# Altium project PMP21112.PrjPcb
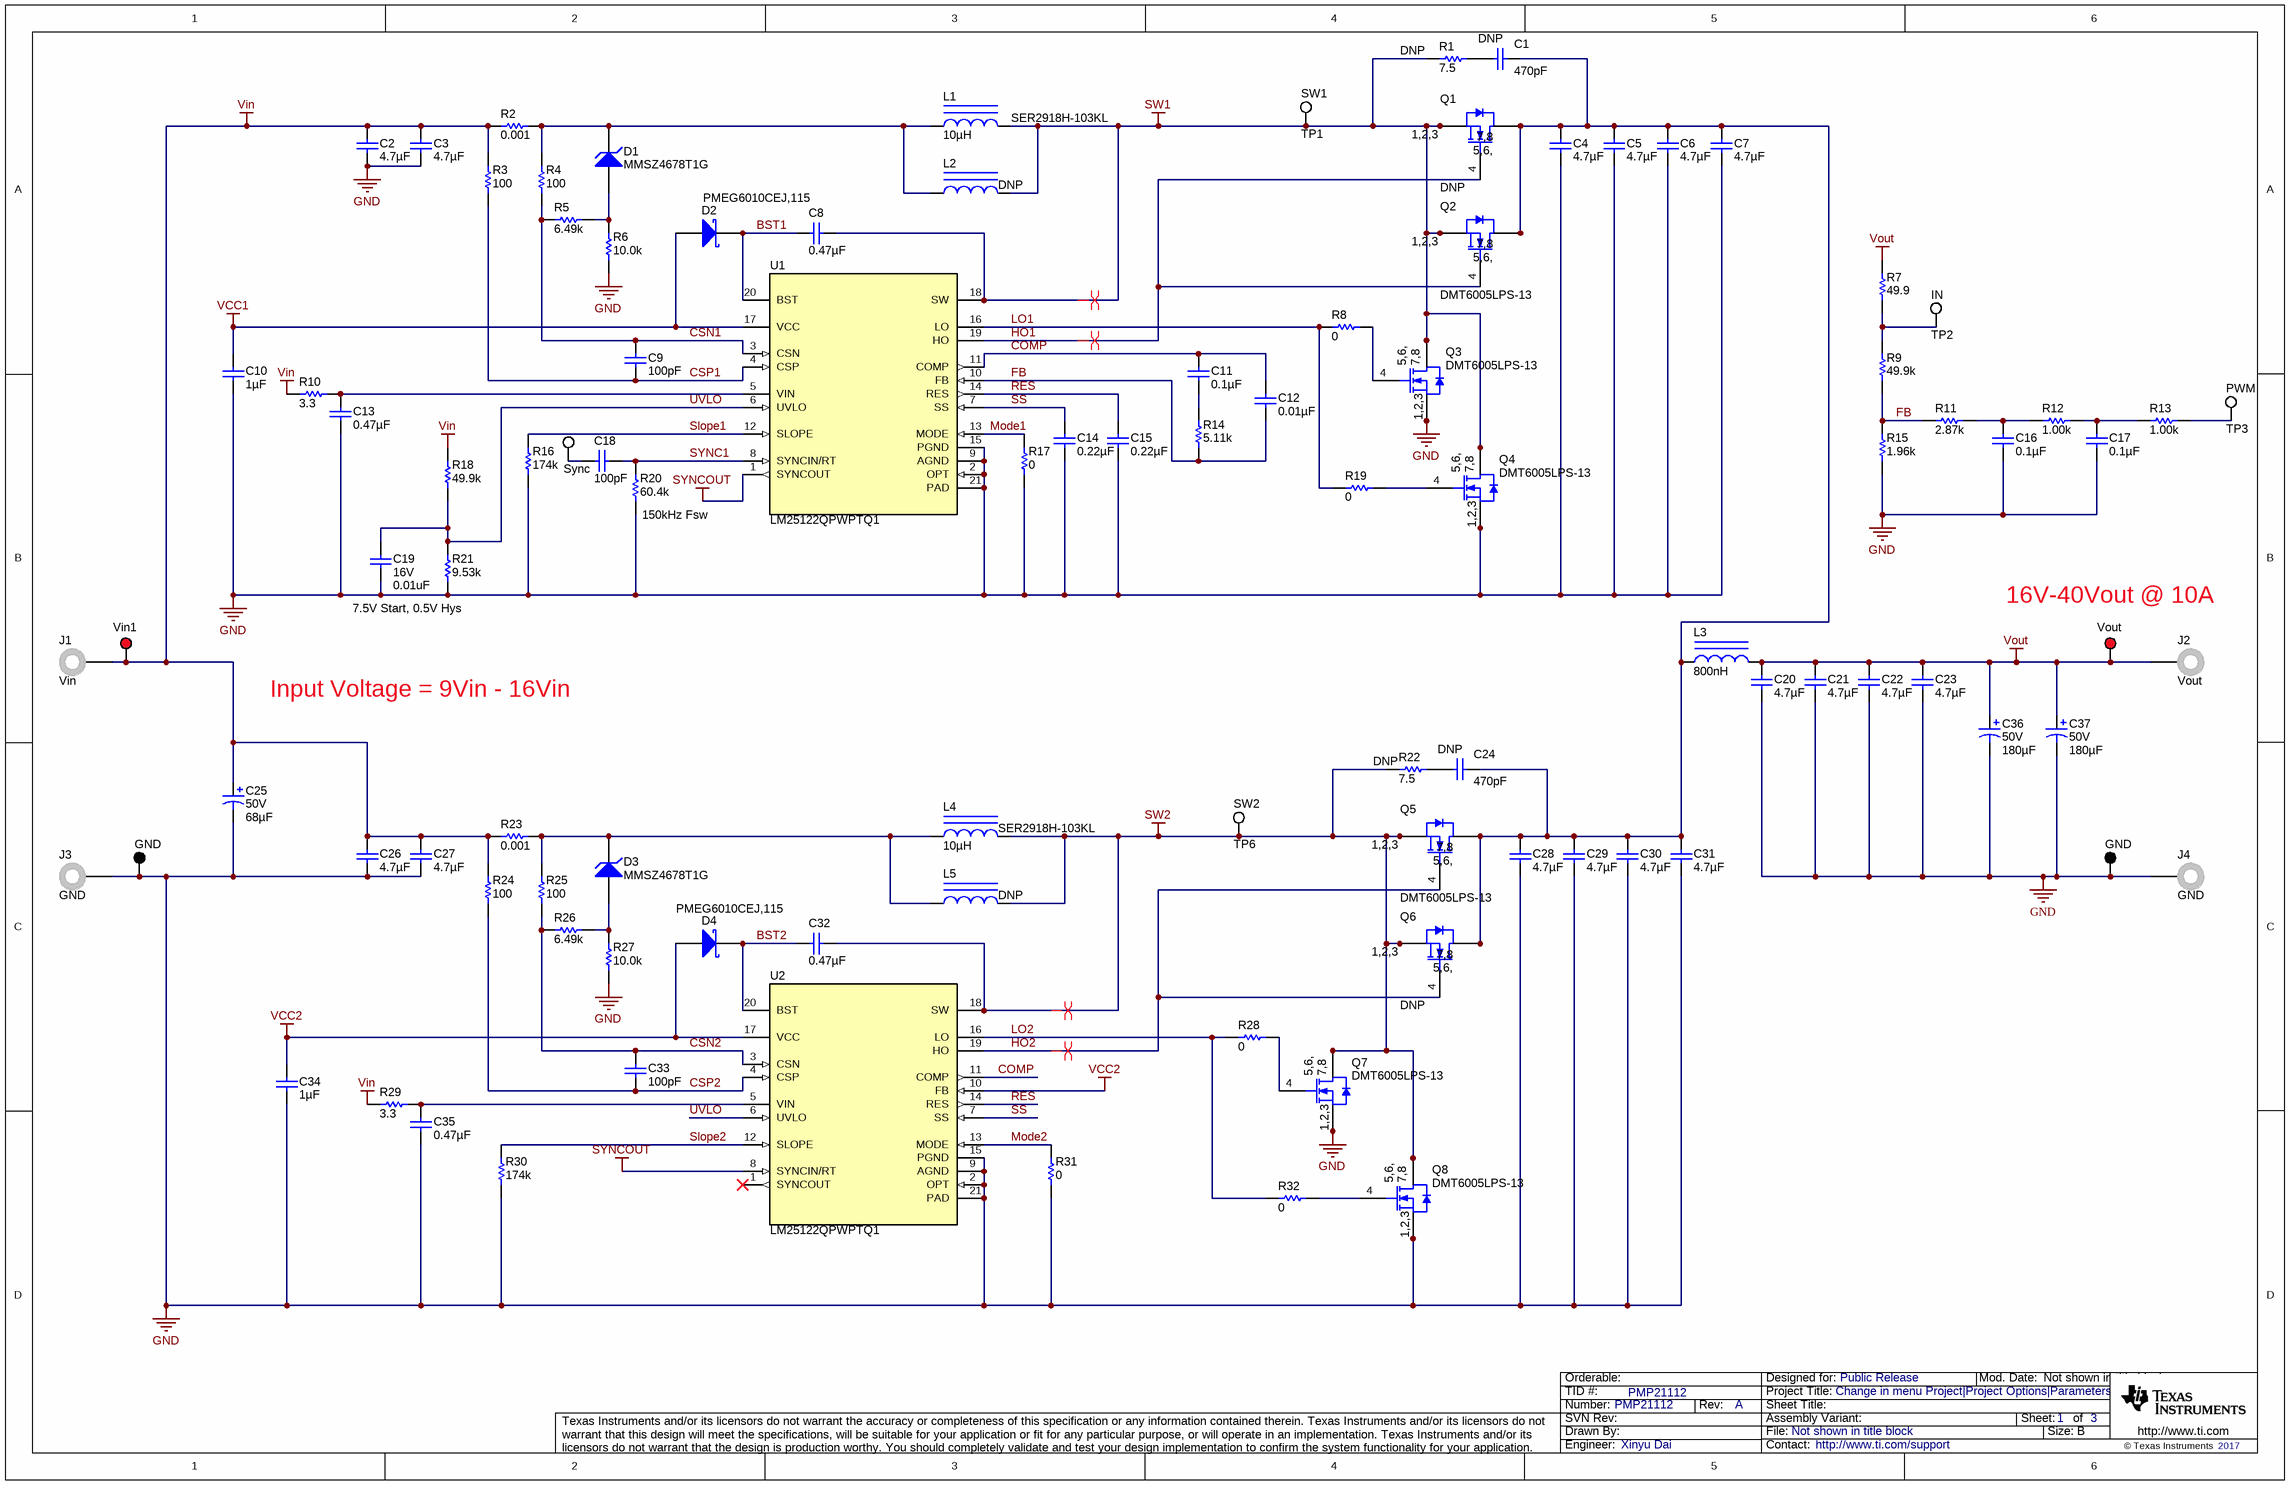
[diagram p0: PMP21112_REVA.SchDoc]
CopyrightYear: 2017; PCB_Layout: Xinyu; PCB_Rev: A; PRJ_Customer: Public Release; PRJ_Engineer: Xinyu Dai; PRJ_Number: PMP21112; PRJ_Title: Change in menu Project|Project Options|Parameters; SCH_Rev: A; TechSupport: http://www.ti.com/support; TID: PMP21112
2 sheets, 111 parts. Net scope: global (net labels, ports and power ports of the same name join across sheets).
Board file: PMP21112_REVA.PcbDoc
Sheets:
  PMP21112_REVA.SchDoc
  PMP21112_REVA_Hardware.SchDoc

## Sheet PMP21112_REVA.SchDoc
size 431 x 279 mm; Date: Not shown in title block; ApprovedBy: Not shown in title block; CheckedBy: Not shown in title block; Author: Not shown in title block; CompanyName: Not shown in title block; Engineer: Not shown in title block; Organization: Not shown in title block; Address1: Not shown in title block; Address2: Not shown in title block; Address3: Not shown in title block; Address4: Not shown in title block; DocumentNumber: 1; Revision: Use project parameter SCH_Rev; SheetNumber: 1; SheetTotal: 3; PageSetup: Record=PageOptions¦CenterHorizontal=True¦CenterVertical=True¦PrintScale=1.00¦XCorrection=1.00¦YCorrection=1.00¦PrintKind=0¦BorderSize=5000000¦LeftOffset=0¦BottomOffset=0¦Orientation=2¦PaperLength=1000¦PaperWidth=1000¦Scale=100¦PaperSource=15¦PrintQuality=600¦MediaType=1¦DitherType=10¦PaperKind=Letter¦PrintScaleMode=1

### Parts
C1  DNP  ValueDisplayed: 470pF  [0805L]
C2  ValueDisplayed: 4.7µF  [1210_270L]  (hidden comment: GRM32ER71K475KE14L)
C3  ValueDisplayed: 4.7µF  [1210_270L]  (hidden comment: GRM32ER71K475KE14L)
C4  ValueDisplayed: 4.7µF  [1210_270L]  (hidden comment: GRM32ER71K475KE14L)
C5  ValueDisplayed: 4.7µF  [1210_270L]  (hidden comment: GRM32ER71K475KE14L)
C6  ValueDisplayed: 4.7µF  [1210_270L]  (hidden comment: GRM32ER71K475KE14L)
C7  ValueDisplayed: 4.7µF  [1210_270L]  (hidden comment: GRM32ER71K475KE14L)
C8  ValueDisplayed: 0.47µF  [0603L]  (hidden comment: CGA3E3X7R1H474K080AE)
C9  ValueDisplayed: 100pF  [0402L]  (hidden comment: GRM1555C1H101JA01D)
C10  ValueDisplayed: 1µF  [0603L]  (hidden comment: GRM188R71E105KA12D)
C11  ValueDisplayed: 0.1µF  [0402L]  (hidden comment: GRM155R71H104ME14D)
C12  ValueDisplayed: 0.01µF  [0402L]  (hidden comment: GRM155R71H103KA88D)
C13  ValueDisplayed: 0.47µF  [0603L]  (hidden comment: CGA3E3X7R1H474K080AE)
C14  ValueDisplayed: 0.22µF  [0402]  (hidden comment: GRM155R71C224KA12D)
C15  ValueDisplayed: 0.22µF  [0402L]  (hidden comment: GRM155R71C224KA12D)
C16  ValueDisplayed: 0.1µF  [0402L]  (hidden comment: GRM155R71H104ME14D)
C17  ValueDisplayed: 0.1µF  [0402L]  (hidden comment: GRM155R71H104ME14D)
C18  ValueDisplayed: 100pF  [0402L]  (hidden comment: GRM1555C1H101JA01D)
C19  VDC_V: 16V  ValueDisplayed: 0.01uF  [0402L]  (hidden comment: GRM155R71C103KA01D)
C20  ValueDisplayed: 4.7µF  [1210_270L]  (hidden comment: GRM32ER71K475KE14L)
C21  ValueDisplayed: 4.7µF  [1210_270L]  (hidden comment: GRM32ER71K475KE14L)
C22  ValueDisplayed: 4.7µF  [1210_270L]  (hidden comment: GRM32ER71K475KE14L)
C23  ValueDisplayed: 4.7µF  [1210_270L]  (hidden comment: GRM32ER71K475KE14L)
C24  DNP  ValueDisplayed: 470pF  [0805L]
C25  VDC_V: 50V  ValueDisplayed: 68µF  [Panasonic_SMT_800x1020]  (hidden comment: EEH-ZA1H680V)
C26  ValueDisplayed: 4.7µF  [1210_270L]  (hidden comment: GRM32ER71K475KE14L)
C27  ValueDisplayed: 4.7µF  [1210_270L]  (hidden comment: GRM32ER71K475KE14L)
C28  ValueDisplayed: 4.7µF  [1210_270L]  (hidden comment: GRM32ER71K475KE14L)
C29  ValueDisplayed: 4.7µF  [1210_270L]  (hidden comment: GRM32ER71K475KE14L)
C30  ValueDisplayed: 4.7µF  [1210_270L]  (hidden comment: GRM32ER71K475KE14L)
C31  ValueDisplayed: 4.7µF  [1210_270L]  (hidden comment: GRM32ER71K475KE14L)
C32  ValueDisplayed: 0.47µF  [0603L]  (hidden comment: CGA3E3X7R1H474K080AE)
C33  ValueDisplayed: 100pF  [0402L]  (hidden comment: GRM1555C1H101JA01D)
C34  ValueDisplayed: 1µF  [0603L]  (hidden comment: GRM188R71E105KA12D)
C35  ValueDisplayed: 0.47µF  [0603L]  (hidden comment: CGA3E3X7R1H474K080AE)
C36  VDC_V: 50V  ValueDisplayed: 180µF  [SM_RADIAL_F]  (hidden comment: EEE-FK1H181SP)
C37  VDC_V: 50V  ValueDisplayed: 180µF  [SM_RADIAL_F]  (hidden comment: EEE-FK1H181SP)
D1  MMSZ4678T1G  [SOD-123]
D2  PMEG6010CEJ,115  [SOD-323F]
D3  MMSZ4678T1G  [SOD-123]
D4  PMEG6010CEJ,115  [SOD-323F]
J1  Vin  [Keystone_575-4]
J2  Vout  [Keystone_575-4]
J3  GND  [Keystone_575-4]
J4  GND  [Keystone_575-4]
L1  SER2918H-103KL  ValueDisplayed: 10µH  [SER2918H]
L2  DNP  [IHLP8787MZ]
L3  ValueDisplayed: 800nH  [XAL7070]  (hidden comment: XAL7070-801MEB)
L4  SER2918H-103KL  ValueDisplayed: 10µH  [SER2918H]
L5  DNP  [IHLP8787MZ]
Q1  DNP  [PowerDI5060-8]
Q2  DMT6005LPS-13  [PowerDI5060-8]
Q3  DMT6005LPS-13  [PowerDI5060-8]
Q4  DMT6005LPS-13  [PowerDI5060-8]
Q5  DMT6005LPS-13  [PowerDI5060-8]
Q6  DNP  [PowerDI5060-8]
Q7  DMT6005LPS-13  [PowerDI5060-8]
Q8  DMT6005LPS-13  [PowerDI5060-8]
R1  DNP  value 7.5  [2010L]
R2  ValueDisplayed: 0.001  [CRE2512-R1_R4]  (hidden comment: CRE2512-FZ-R001E-3)
R3  ValueDisplayed: 100  [0402L]  (hidden comment: CRCW0402100RFKED)
R4  ValueDisplayed: 100  [0402L]  (hidden comment: CRCW0402100RFKED)
R5  ValueDisplayed: 6.49k  [0402]  (hidden comment: CRCW04026K49FKED)
R6  ValueDisplayed: 10.0k  [0402L]  (hidden comment: CRCW040210K0FKED)
R7  ValueDisplayed: 49.9  [0402L]  (hidden comment: CRCW040249R9FKED)
R8  ValueDisplayed: 0  [0402L]  (hidden comment: CRCW04020000Z0ED)
R9  ValueDisplayed: 49.9k  [0402L]  (hidden comment: CRCW040249K9FKED)
R10  ValueDisplayed: 3.3  [0603L]  (hidden comment: CRCW06033R30JNEA)
R11  ValueDisplayed: 2.87k  [0402L]  (hidden comment: CRCW04022K87FKED)
R12  ValueDisplayed: 1.00k  [0402L]  (hidden comment: CRCW04021K00FKED)
R13  ValueDisplayed: 1.00k  [0402L]  (hidden comment: CRCW04021K00FKED)
R14  ValueDisplayed: 5.11k  [0402L]  (hidden comment: CRCW04025K11FKED)
R15  ValueDisplayed: 1.96k  [0402L]  (hidden comment: CRCW04021K96FKED)
R16  ValueDisplayed: 174k  [0402L]  (hidden comment: CRCW0402174KFKED)
R17  ValueDisplayed: 0  [0402L]  (hidden comment: CRCW04020000Z0ED)
R18  ValueDisplayed: 49.9k  [0402L]  (hidden comment: CRCW040249K9FKED)
R19  ValueDisplayed: 0  [0402L]  (hidden comment: CRCW04020000Z0ED)
R20  ValueDisplayed: 60.4k  [0402L]  (hidden comment: CRCW040260K4FKED)
R21  ValueDisplayed: 9.53k  [0402L]  (hidden comment: CRCW04029K53FKED)
R22  DNP  value 7.5  [2010L]
R23  ValueDisplayed: 0.001  [CRE2512-R1_R4]  (hidden comment: CRE2512-FZ-R001E-3)
R24  ValueDisplayed: 100  [0402L]  (hidden comment: CRCW0402100RFKED)
R25  ValueDisplayed: 100  [0402L]  (hidden comment: CRCW0402100RFKED)
R26  ValueDisplayed: 6.49k  [0402L]  (hidden comment: CRCW04026K49FKED)
R27  ValueDisplayed: 10.0k  [0402L]  (hidden comment: CRCW040210K0FKED)
R28  ValueDisplayed: 0  [0402L]  (hidden comment: CRCW04020000Z0ED)
R29  ValueDisplayed: 3.3  [0603L]  (hidden comment: CRCW06033R30JNEA)
R30  ValueDisplayed: 174k  [0402L]  (hidden comment: CRCW0402174KFKED)
R31  ValueDisplayed: 0  [0402L]  (hidden comment: CRCW04020000Z0ED)
R32  ValueDisplayed: 0  [0402L]  (hidden comment: CRCW04020000Z0ED)
Sync  5002  [Keystone5002]  (value not drawn)
TP1  SW1  [Keystone5002]
TP2  IN  [Keystone5002]
TP3  PWM  [Keystone5002]
TP4  GND  [Keystone5001]
TP5  GND  [Keystone5001]
TP6  SW2  [Keystone5002]
U1  LM25122QPWPTQ1  [PWP0020A_N]
U2  LM25122QPWPTQ1  [PWP0020A_N]
Vin1  5000  [Keystone5000]  (value not drawn)
Vout  5000  [Keystone5000]  (value not drawn)

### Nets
GND: C2.2 C3.2 C4.2 C5.2 C6.2 C7.2 C10.2 C13.2 C14.2 C15.2 C16.2 C17.2 C19.2 C20.2 C21.2 C22.2 C23.2 C25.2(-) C26.2 C27.2 C28.2 C29.2 C30.2 C31.2 C34.2 C35.2 C36.2(-) C37.2(-) J3.1 J4.1 Q3.1(S) Q3.2(S) Q3.3(S) Q4.1(S) Q4.2(S) Q4.3(S) Q7.1(S) Q7.2(S) Q7.3(S) Q8.1(S) Q8.2(S) Q8.3(S) R6.1 R15.1 R16.1 R17.1 R20.1 R21.1 R27.1 R30.1 R31.1 TP4.1 TP5.1 U1.2(OPT) U1.9(AGND) U1.15(PGND) U1.21(PAD) U2.2(OPT) U2.9(AGND) U2.15(PGND) U2.21(PAD)
SW1: C8.2 L1.1 L2.1 Q1.1(S) Q1.2(S) Q1.3(S) Q2.1(S) Q2.2(S) Q2.3(S) Q3.5(D) Q3.6(D) Q3.7(D) Q3.8(D) Q3.9(D) Q4.5(D) Q4.6(D) Q4.7(D) Q4.8(D) Q4.9(D) R1.2 TP1.1 U1.18(SW)
SW2: C32.2 L4.2 L5.1 Q5.1(S) Q5.2(S) Q5.3(S) Q6.1(S) Q6.2(S) Q6.3(S) Q7.5(D) Q7.6(D) Q7.7(D) Q7.8(D) Q7.9(D) Q8.5(D) Q8.6(D) Q8.7(D) Q8.8(D) Q8.9(D) R22.2 TP6.1 U2.18(SW)
SYNCOUT: U1.1(SYNCOUT) U2.8(SYNCIN/RT)
VCC1: C10.1 D2.2(A) U1.17(VCC)
VCC2: C34.1 D4.2(A) U2.10(FB) U2.17(VCC)
Vin: C2.1 C3.1 C25.1(+) C26.1 C27.1 J1.1 R2.1 R3.2 R10.1 R18.2 R23.1 R24.2 R29.1 Vin1.1
Vout: C20.1 C21.1 C22.1 C23.1 C36.1(+) C37.1(+) J2.1 L3.2 R7.1 Vout.1
BST1: C8.1 D2.1(K) U1.20(BST)
BST2: C32.1 D4.1(K) U2.20(BST)
COMP: C11.1 C12.1 U1.11(COMP) U2.11(COMP)
CSN1: C9.1 R4.1 R5.1 U1.3(CSN)
CSN2: C33.1 R25.1 R26.1 U2.3(CSN)
CSP1: C9.2 R3.1 U1.4(CSP)
CSP2: C33.2 R24.1 U2.4(CSP)
FB: C12.2 R9.2 R11.1 R14.1 R15.2 U1.10(FB)
HO1: Q1.4(G) Q2.4(G) U1.19(HO)
HO2: Q5.4(G) Q6.4(G) U2.19(HO)
LO1: R8.2 R19.2 U1.16(LO)
LO2: R28.2 R32.2 U2.16(LO)
Mode1: R17.2 U1.13(MODE)
Mode2: R31.2 U2.13(MODE)
RES: C15.1 U1.14(RES) U2.14(RES)
Slope1: R16.2 U1.12(SLOPE)
Slope2: R30.2 U2.12(SLOPE)
SS: C14.1 U1.7(SS) U2.7(SS)
SYNC1: C18.1 R20.2 U1.8(SYNCIN/RT)
UVLO: C19.1 R18.1 R21.2 U1.6(UVLO) U2.6(UVLO)
NetC1_1: C1.1 C4.1 C5.1 C6.1 C7.1 C24.1 C28.1 C29.1 C30.1 C31.1 L3.1 Q1.5(D) Q1.6(D) Q1.7(D) Q1.8(D) Q1.9(D) Q2.5(D) Q2.6(D) Q2.7(D) Q2.8(D) Q2.9(D) Q5.5(D) Q5.6(D) Q5.7(D) Q5.8(D) Q5.9(D) Q6.5(D) Q6.6(D) Q6.7(D) Q6.8(D) Q6.9(D)
NetC1_2: C1.2 R1.1
NetC11_2: C11.2 R14.2
NetC13_1: C13.1 R10.2 U1.5(VIN)
NetC16_1: C16.1 R11.2 R12.1
NetC17_1: C17.1 R12.2 R13.1
NetC18_2: C18.2 Sync.1
NetC24_2: C24.2 R22.1
NetC35_1: C35.1 R29.2 U2.5(VIN)
NetD1_1: D1.1(K) L1.2 L2.2 R2.2 R4.2
NetD1_2: D1.2(A) R5.2 R6.2
NetD3_1: D3.1(K) L4.1 L5.2 R23.2 R25.2
NetD3_2: D3.2(A) R26.2 R27.2
NetQ3_4: Q3.4(G) R8.1
NetQ4_4: Q4.4(G) R19.1
NetQ7_4: Q7.4(G) R28.1
NetQ8_4: Q8.4(G) R32.1
NetR7_2: R7.2 R9.1 TP2.1
NetR13_2: R13.2 TP3.1

Not connected (* = marked no-connect by the designer): U2 1(SYNCOUT)*

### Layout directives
differential pair: HO1, HO2, SW1, SW2

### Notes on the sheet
- (near R20) 150kHz Fsw
- 7.5V Start, 0.5V Hys
- 16V-40Vout @ 10A
- Input Voltage = 9Vin - 16Vin

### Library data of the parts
C1 C24 = GRM2165C2A471JA01D: CAP, CERM, 470pF, 100V, +/-5%, C0G/NP0, 0805; Manufacturer: MuRata; Polarized: N; CompType: Capacitor; U/M: EA; Cap_F: 0.00000000047; Tolerance_%: 5; VDC_V: 100; TaMin_C: -55; TaMax_C: 125; Cap_Case: 0805
C2-C7 C20-C23 C26-C31 = GRM32ER71K475KE14L: CAP, CERM, 4.7 µF, 80 V, +/- 10%, X7R, 1210; Manufacturer: MuRata; Polarized: N; CompType: Capacitor; Value: 4.7uF; U/M: EA; Cap_F: 0.0000047; Tolerance_%: 10; Value1: Unknown; VDC_V: 80; Value2: 80V; TaMin_C: -55; TaMax_C: 125; Cap_Case: 1210; SizeArea_mm2: 8; SizeAreaWB_mm2: 14.7; SizeX_mm: 3.2; SizeY_mm: 2.5; SizeZ_mm: 2.7; AEC Category: Q200
C8 C13 C32 C35 = CGA3E3X7R1H474K080AE: CAP, CERM, 0.47 µF, 50 V,+/- 10%, X7R, AEC-Q200 Grade 1, 0603; Manufacturer: TDK; Polarized: N; CompType: Capacitor; Value: 0.47uF; U/M: EA; Cap_F: 0.00000047; Tolerance_%: 10; VDC_V: 50; Value2: 50V; TaMin_C: -55; TaMax_C: 125; Cap_Case: 0603; SizeArea_mm2: 1.28; SizeAreaWB_mm2: 4.68; SizeX_mm: 1.6; SizeY_mm: 0.8; SizeZ_mm: 1; AEC Category: Q200; AEC Qualified: Y
C9 C18 C33 = GRM1555C1H101JA01D: CAP, CERM, 100 pF, 50 V,+/- 5%, C0G/NP0, 0402; Manufacturer: MuRata; Polarized: N; CompType: Capacitor; Value: 100pF; U/M: EA; Cap_F: 0.0000000001; Tolerance_%: 5; VDC_V: 50; Value2: 50V; TaMin_C: -55; TaMax_C: 125; Cap_Case: 0402; SizeArea_mm2: 0.5; SizeAreaWB_mm2: 3; SizeX_mm: 1; SizeZ_mm: 0.6; AEC Category: Q200; Green_Lifecycle: Active; Green_REACh: Passed
C10 C34 = GRM188R71E105KA12D: CAP, CERM, 1uF, 25V, +/-10%, X7R, 0603; Manufacturer: MuRata; Polarized: N; CompType: Capacitor; U/M: EA; Cap_F: 0.000001; Tolerance_%: 10; VDC_V: 25; TaMin_C: -55; TaMax_C: 125; Cap_Case: 0603
C11 C16 C17 = GRM155R71H104ME14D: CAP, CERM, 0.1 µF, 50 V,+/- 20%, X7R, 0402; Manufacturer: MuRata; Polarized: N; CompType: Capacitor; Value: 0.1uF; U/M: EA; Cap_F: 0.0000001; Tolerance_%: 20; VDC_V: 50; Value2: 50V; TaMin_C: -55; TaMax_C: 125; Cap_Case: 0402; SizeArea_mm2: 0.5; SizeAreaWB_mm2: 3; SizeX_mm: 1; SizeZ_mm: 0.6; AEC Category: Q200
C12 = GRM155R71H103KA88D: CAP, CERM, 0.01 µF, 50 V,+/- 10%, X7R, 0402; Manufacturer: MuRata; Polarized: N; CompType: Capacitor; Value: 0.01uF; U/M: EA; Cap_F: 0.00000001; Tolerance_%: 10; VDC_V: 50; Value2: 50V; TaMin_C: -55; TaMax_C: 125; Cap_Case: 0402; SizeArea_mm2: 0.5; SizeAreaWB_mm2: 3; SizeX_mm: 1; SizeZ_mm: 0.6; AEC Category: Q200; Green_Lifecycle: Active; Green_REACh: Passed
C14 = GRM155R71C224KA12D: CAP, CERM, 0.22 µF, 16 V,+/- 10%, X7R, 0402; Manufacturer: MuRata; Polarized: N; CompType: Capacitor; Value: 0.22uF; U/M: EA; Cap_F: 0.00000022; Tolerance_%: 10; VDC_V: 16; Value2: 16V; TaMin_C: -55; TaMax_C: 125; SizeArea_mm2: 0.5; SizeAreaWB_mm2: 3; SizeX_mm: 1; SizeZ_mm: 0.6; AEC Category: Q200; Green_Lifecycle: Active; Green_REACh: Passed
C15 = GRM155R71C224KA12D: CAP, CERM, 0.22 µF, 16 V,+/- 10%, X7R, 0402; Manufacturer: MuRata; Polarized: N; CompType: Capacitor; Value: 0.22uF; U/M: EA; Cap_F: 0.00000022; Tolerance_%: 10; VDC_V: 16; Value2: 16V; TaMin_C: -55; TaMax_C: 125; Cap_Case: 0402; SizeArea_mm2: 0.5; SizeAreaWB_mm2: 3; SizeX_mm: 1; SizeZ_mm: 0.6; AEC Category: Q200; Green_Lifecycle: Active; Green_REACh: Passed
C19 = CMP-0006639-2: CAP, CERM, 0.01 uF, 16 V, +/- 10%, X7R, 0402; Manufacturer: MuRata; TaMin_C: -55°C; Polarized: N; SizeAreaWB_mm2: 3; Value1: Unknown; U/M: EA; Value: 0.01uF; TaMax_C: 125°C; SizeZ_mm: 0.6; SizeX_mm: 1; SizeY_mm: 0.5; Cap_Case: 0402; Cap_F: 10nF; AEC Category: Q200
C25 = CMP-0077288-1: CAP, Aluminum Polymer, 68 µF, 50 V,+/- 20%, 0.03 ohm, AEC-Q200 Grade 2, D8xL10.2mm SMD; Manufacturer: Panasonic; IRMS_A: 1.8A; SizeAreaWB_mm2: 106.09; SizeArea_mm2: 68.89; AEC Qualified: Y; AEC Category: Q200; Value: 68uF; TaMax_C: 105°C; SizeZ_mm: 10.5; AEC Grade: 2; TaMin_C: -55°C; SizeY_mm: 8.3; U/M: EA; CompType: Capacitor; ESR_ohm: 0.03; Cap_Case: 8x10.2mm
C36 C37 = CMP-0078149-1: CAP, AL, 180 µF, 50 V, +/- 20%, 0.34 ohm, AEC-Q200 Grade 2, SMD; Manufacturer: Panasonic; IRMS_A: 3.5dA; SizeAreaWB_mm2: 123.6; SizeArea_mm2: 83; AEC Qualified: Y; AEC Category: Q200; Value: 180uF; TaMax_C: 105°C; SizeZ_mm: 10.2; AEC Grade: 2; TaMin_C: -55°C; SizeY_mm: 8.3; U/M: EA; CompType: Capacitor; SizeX_mm: 10; ESR_ohm: 3.4d; Cap_Case: 8X10.2mm
D1 D3 = CMP-0005776-1: Diode, Zener, 1.8 V, 500 mW, SOD-123; Manufacturer: ON Semiconductor; Power_W: 500mW; SizeAreaWB_mm2: 13.095; Vz_V: 1.8V; Value1: 0.5W; RJA_CperW: 340; U/M: EA; Value: 1.8V; SizeZ_mm: 1.35; SizeX_mm: 3.85; SizeY_mm: 1.7; SizeArea_mm2: 6.545; AEC Category: Q101
D2 D4 = PMEG6010CEJ,115: Diode, Schottky, 60 V, 1 A, SOD-323F; Manufacturer: Nexperia; U/M: EA; Vf_V: 0.66; Value: 60V; Value1: 1A; Value2: 0.66V; Io_A: 1; Vr_V: 60; TJmax_C: 150; SizeAreaWB_mm2: 7.875; SizeArea_mm2: 3.125; SizeX_mm: 2.5; SizeY_mm: 1.25; SizeZ_mm: 0.8; AEC Category: Q101; Green_Lifecycle: Not Set; Green_REACh: Incomplete
J1-J4 = 575-4: Standard Banana Jack, Uninsulated, 5.5mm; Manufacturer: Keystone; Alternate Manufacturer: Any; Alternate PartNumber: Equivalent; CompType: Connector; U/M: EA
L1 L4 = SER2918H-103KL: Inductor, Shielded E Core, Ferrite, 10 µH, 28 A, 0.0026 ohm, SMD; Manufacturer: Coilcraft; Value: 10uH; Ind_H: 10.0E-6; Imax_A: 28; Irms: 28A @ 40C rise; Isat: 32.1A @ 30% inductance drop; DCR_ohm: 0.0026; Value2: 28A; SizeAreaWB_mm2: 651.82; SizeArea_mm2: 552.42; SizeX_mm: 27.9; SizeY_mm: 19.8; SizeZ_mm: 17.78; AEC Category: Q200; Green_Lifecycle: Not Set; Green_REACh: Incomplete
L2 L5 = CMP-0063541-1: Inductor, Shielded, 10 uH, 28 A, 0.00404 ohm, AEC-Q200 Grade 0, SMD; Manufacturer: Vishay-Dale; PartNumber: IHLP8787MZER100M5A; Isat: 28A @ 20% inductance drop; Irms: 28A @ 40C rise; Green_Lifecycle: Active; SizeAreaWB_mm2: 587.52; DCR_ohm: 4.04m; Green_REACh: Passed; Value: 10uH; Imax_A: 28A; SizeZ_mm: 13; SizeX_mm: 22.48; SizeY_mm: 22; SizeArea_mm2: 494.56; Ind_H: 10µH; AEC Qualified: Y; AEC Grade: 0; AEC Category: Q200
L3 = CMP-0061058-1: Inductor, Shielded, Composite, 800 nH, 25.8 A, 0.00208 ohm, SMD; Manufacturer: Coilcraft; Isat: 37.8A @ 30% inductance drop; Irms: 25.8A @ 40C rise; Green_Lifecycle: Not Set; SizeAreaWB_mm2: 87.4; DCR_ohm: 2.08m; Green_REACh: Incomplete; Value: 800nH; Imax_A: 25.8A; SizeZ_mm: 7; SizeX_mm: 7.2; SizeY_mm: 7.5; SizeArea_mm2: 54; AEC Category: Q200
Q1 Q6 = CMP-0067552-1: MOSFET, N-CH, 60 V, 17.9 A, AEC-Q101, 8-PowerTDFN; Alternate Manufacturer: None; Manufacturer: Diodes Inc.; PartNumber: DMT6005LPS-13; Rdson45_ohm: 8.5m; QgTyp_nC: 47.1; SizeAreaWB_mm2: 58.2725; Vgs_V: 20V; Value1: 0.0085 ohm; VdsMax_V: 60V; U/M: EA; Value: 60V; IdsMax_A: 17.9A; SizeZ_mm: 1.1; SizeX_mm: 6.15; SizeY_mm: 5.15; Value2: 47.1 nC; SizeArea_mm2: 31.6725; ChType: N; AEC Qualified: Y; AEC Category: Q101
Q2-Q5 Q7 Q8 = CMP-0067552-1: MOSFET, N-CH, 60 V, 17.9 A, AEC-Q101, 8-PowerTDFN; Alternate Manufacturer: None; Manufacturer: Diodes Inc.; Rdson45_ohm: 8.5m; QgTyp_nC: 47.1; SizeAreaWB_mm2: 58.2725; Vgs_V: 20V; Value1: 0.0085 ohm; VdsMax_V: 60V; U/M: EA; Value: 60V; IdsMax_A: 17.9A; SizeZ_mm: 1.1; SizeX_mm: 6.15; SizeY_mm: 5.15; Value2: 47.1 nC; SizeArea_mm2: 31.6725; ChType: N; AEC Qualified: Y; AEC Category: Q101
R1 R22 = ERJ-12ZYJ7R5U: RESISTOR 7.5 OHM 3/4W 5% 2010; Manufacturer: Panasonic; Value_Code: 7R50; Tolerance_%: 5; Power_W: 1; Value2: 1W; VDC_V: 3; TempCo: -100 /+600 ppm/C; EIA_Code: E24; U/M: EA
R2 R23 = CMP-0015748-2: RES, 0.001, 1%, 3 W, AEC-Q200 Grade 0, 2512; Manufacturer: Bourns; Power_W: 3W; TempCo: 50 ppm/C; Value_Code: 1L000; U/M: EA; Value: 0.001; EIA_Code: E96; Res_ohm: 1m; SizeX_mm: 6.45; SizeY_mm: 3.35; SizeZ_mm: 0.9; SizeArea_mm2: 21.6075; CompType: Resistor; AEC Qualified: Y; AEC Grade: 0; AEC Category: Q200
R3 R4 R24 R25 = CRCW0402100RFKED: RES, 100, 1%, 0.063 W, 0402; Manufacturer: Vishay-Dale; CompType: Resistor; Value: 100; Value_Code: 100R; Tolerance_%: 1; Power_W: 0.063; Value2: 0.063W; VDC_V: 50; TempCo: 100 ppm/C; SizeArea_mm2: 0.5; SizeZ_mm: 0.6; EIA_Code: E96; U/M: EA; AEC Category: Q200; Green_Lifecycle: Active; Green_REACh: Passed
R5 R26 = CRCW04026K49FKED: RES, 6.49 k, 1%, 0.063 W, 0402; Manufacturer: Vishay-Dale; CompType: Resistor; Value: 6.49k; Res_ohm: 6490; Value_Code: 6k49; Tolerance_%: 1; Power_W: 0.063; Value2: 0.063W; VDC_V: 50; TempCo: 100 ppm/C; SizeArea_mm2: 0.5; SizeZ_mm: 0.6; EIA_Code: E96; U/M: EA; AEC Category: Q200; Green_Lifecycle: Active; Green_REACh: Passed
R6 R27 = CRCW040210K0FKED: RES, 10.0 k, 1%, 0.063 W, 0402; Manufacturer: Vishay-Dale; CompType: Resistor; Value: 10.0k; Res_ohm: 10000; Value_Code: 10k0; Tolerance_%: 1; Power_W: 0.063; Value2: 0.063W; VDC_V: 50; TempCo: 100 ppm/C; SizeArea_mm2: 0.5; SizeZ_mm: 0.6; EIA_Code: E96; U/M: EA; AEC Category: Q200; Green_Lifecycle: Active; Green_REACh: Passed
R7 = CRCW040249R9FKED: RES, 49.9, 1%, 0.063 W, 0402; Manufacturer: Vishay-Dale; CompType: Resistor; Value: 49.9; Value_Code: 49R9; Tolerance_%: 1; Power_W: 0.063; Value2: 0.063W; VDC_V: 50; TempCo: 100 ppm/C; SizeArea_mm2: 0.5; SizeZ_mm: 0.6; EIA_Code: E96; U/M: EA; AEC Category: Q200; Green_Lifecycle: Active; Green_REACh: Passed
R8 R17 R19 R28 R31 R32 = CRCW04020000Z0ED: RES, 0, 5%, 0.063 W, 0402; Manufacturer: Vishay-Dale; CompType: Resistor; Value: 0; Value_Code: 0000; Tolerance_%: 5; Power_W: 0.063; Value2: 0.063W; VDC_V: 50; TempCo: 200 ppm/C; SizeArea_mm2: 0.5; SizeX_mm: 1; SizeZ_mm: 0.6; EIA_Code: E24; U/M: EA; AEC Category: Q200; Green_Lifecycle: Active; Green_REACh: Passed
R9 R18 = CRCW040249K9FKED: RES, 49.9 k, 1%, 0.063 W, 0402; Manufacturer: Vishay-Dale; CompType: Resistor; Value: 49.9k; Res_ohm: 49900; Value_Code: 49k9; Tolerance_%: 1; Power_W: 0.063; Value2: 0.063W; VDC_V: 50; TempCo: 100 ppm/C; SizeArea_mm2: 0.5; SizeZ_mm: 0.6; EIA_Code: E96; U/M: EA; AEC Category: Q200; Green_Lifecycle: Active; Green_REACh: Passed
R10 R29 = CRCW06033R30JNEA: RES, 3.3, 5%, 0.1 W, 0603; Manufacturer: Vishay-Dale; CompType: Resistor; Value: 3.3; Value_Code: 3R30; Tolerance_%: 5; Power_W: 0.1; Value2: 0.1W; VDC_V: 75; TempCo: 200 ppm/C; SizeArea_mm2: 1.28; SizeX_mm: 1.6; SizeY_mm: 0.8; SizeZ_mm: 1; EIA_Code: E24; U/M: EA; AEC Category: Q200; Green_Lifecycle: Active; Green_REACh: Passed
R11 = CRCW04022K87FKED: RES, 2.87 k, 1%, 0.063 W, 0402; Manufacturer: Vishay-Dale; CompType: Resistor; Value: 2.87k; Res_ohm: 2870; Value_Code: 2k87; Tolerance_%: 1; Power_W: 0.063; Value2: 0.063W; VDC_V: 50; TempCo: 100 ppm/C; SizeArea_mm2: 0.5; SizeZ_mm: 0.6; EIA_Code: E96; U/M: EA; AEC Category: Q200
R12 R13 = CRCW04021K00FKED: RES, 1.00 k, 1%, 0.063 W, 0402; Manufacturer: Vishay-Dale; CompType: Resistor; Value: 1.00k; Res_ohm: 1000; Value_Code: 1k00; Tolerance_%: 1; Power_W: 0.063; Value2: 0.063W; VDC_V: 50; TempCo: 100 ppm/C; SizeArea_mm2: 0.5; SizeZ_mm: 0.6; EIA_Code: E96; U/M: EA; AEC Category: Q200; Green_Lifecycle: Active; Green_REACh: Passed
R14 = CRCW04025K11FKED: RES, 5.11 k, 1%, 0.063 W, 0402; Manufacturer: Vishay-Dale; CompType: Resistor; Value: 5.11k; Res_ohm: 5110; Value_Code: 5k11; Tolerance_%: 1; Power_W: 0.063; Value2: 0.063W; VDC_V: 50; TempCo: 100 ppm/C; SizeArea_mm2: 0.5; SizeZ_mm: 0.6; EIA_Code: E96; U/M: EA; AEC Category: Q200; Green_Lifecycle: Active; Green_REACh: Passed
R15 = CRCW04021K96FKED: RES, 1.96 k, 1%, 0.063 W, 0402; Manufacturer: Vishay-Dale; CompType: Resistor; Value: 1.96k; Res_ohm: 1960; Value_Code: 1k96; Tolerance_%: 1; Power_W: 0.063; Value2: 0.063W; VDC_V: 50; TempCo: 100 ppm/C; SizeArea_mm2: 0.5; SizeZ_mm: 0.6; EIA_Code: E96; U/M: EA; AEC Category: Q200
R16 R30 = CRCW0402174KFKED: RES, 174 k, 1%, 0.063 W, 0402; Manufacturer: Vishay-Dale; CompType: Resistor; Value: 174k; Res_ohm: 174000; Tolerance_%: 1; Power_W: 0.063; Value2: 0.063W; VDC_V: 50; TempCo: 100 ppm/C; SizeArea_mm2: 0.5; SizeZ_mm: 0.6; EIA_Code: E96; U/M: EA; AEC Category: Q200; Green_Lifecycle: Not Set; Green_REACh: Incomplete
R20 = CRCW040260K4FKED: RES, 60.4 k, 1%, 0.063 W, 0402; Manufacturer: Vishay-Dale; CompType: Resistor; Value: 60.4k; Res_ohm: 60400; Value_Code: 60k4; Tolerance_%: 1; Power_W: 0.063; Value2: 0.063W; VDC_V: 50; TempCo: 100 ppm/C; SizeArea_mm2: 0.5; SizeZ_mm: 0.6; EIA_Code: E96; U/M: EA; AEC Category: Q200; Green_Lifecycle: Active; Green_REACh: Passed
R21 = CRCW04029K53FKED: RES, 9.53 k, 1%, 0.063 W, 0402; Manufacturer: Vishay-Dale; CompType: Resistor; Value: 9.53k; Res_ohm: 9530; Value_Code: 9k53; Tolerance_%: 1; Power_W: 0.063; Value2: 0.063W; VDC_V: 50; TempCo: 100 ppm/C; SizeArea_mm2: 0.5; SizeZ_mm: 0.6; EIA_Code: E96; U/M: EA; AEC Category: Q200; Green_Lifecycle: Active; Green_REACh: Passed
Sync TP1-TP3 TP6 = 5002: Test Point, TH, Miniature, White; Manufacturer: Keystone; Alternate Manufacturer: Any; Alternate PartNumber: Equivalent; CompType: Test Point Loop; U/M: EA
TP4 TP5 = 5001: Test Point, TH, Miniature, Black; Manufacturer: Keystone; CompType: Test Point Loop; U/M: EA
U1 U2 = LM25122QPWPTQ1: Automotive Grade, 3-42V Wide Vin, Synchronous Boost Controller with Multiphase Capability, PWP0020A (TSSOP-20); Manufacturer: Texas Instruments; SymbolCreator: Altium; SizeArea_mm2: 41.6; SizeAreaWB_mm2: 71.4; SizeX_mm: 6.4; SizeY_mm: 6.5; SizeZ_mm: 1.2; CompType: IC; U/M: EA
Vin1 Vout = 5000: Test Point, TH, Miniature, Red; Manufacturer: Keystone; CompType: Test Point Loop; U/M: EA

## Sheet PMP21112_REVA_Hardware.SchDoc
size 431 x 279 mm; Date: Not shown in title block; ApprovedBy: Not shown in title block; CheckedBy: Not shown in title block; Author: Not shown in title block; CompanyName: Not shown in title block; Engineer: Not shown in title block; Organization: Not shown in title block; Address1: Not shown in title block; Address2: Not shown in title block; Address3: Not shown in title block; Address4: Not shown in title block; DocumentNumber: 3; Revision: Use project parameter SCH_Rev; SheetNumber: 3; SheetTotal: 3; PageSetup: Record=PageOptions¦CenterHorizontal=True¦CenterVertical=True¦PrintScale=1.00¦XCorrection=1.00¦YCorrection=1.00¦PrintKind=0¦BorderSize=5000000¦LeftOffset=0¦BottomOffset=0¦Orientation=2¦PaperLength=1000¦PaperWidth=1000¦Scale=100¦PaperSource=15¦PrintQuality=600¦MediaType=1¦DitherType=10¦PaperKind=Letter¦PrintScaleMode=1
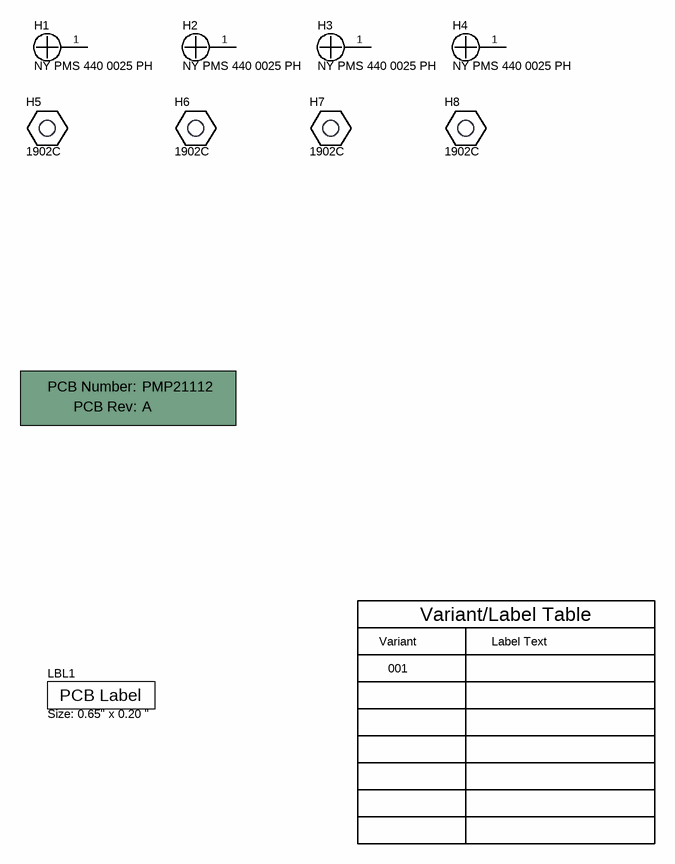
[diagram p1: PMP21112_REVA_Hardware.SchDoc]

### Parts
!PCB1  Printed Circuit Board  (value not drawn)  (mechanical)
H1  NY PMS 440 0025 PH  [NY PMS 440 0025 PH]
H2  NY PMS 440 0025 PH  [NY PMS 440 0025 PH]
H3  NY PMS 440 0025 PH  [NY PMS 440 0025 PH]
H4  NY PMS 440 0025 PH  [NY PMS 440 0025 PH]
H5  1902C  [Keystone_1902C]
H6  1902C  [Keystone_1902C]
H7  1902C  [Keystone_1902C]
H8  1902C  [Keystone_1902C]
LBL1  Size: 0.65" x 0.20 "  [Label_650x200]

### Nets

Not connected (* = marked no-connect by the designer): H1 1; H2 1; H3 1; H4 1

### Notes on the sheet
- Variant
- Variant/Label Table
- Label Text
- 001

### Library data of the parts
!PCB1 = PCB: Manufacturer: Any; PartNumber: PMP21112; SymbolCreator: a0412235
H1-H4 = NY PMS 440 0025 PH: Machine Screw, Round, #4-40 x 1/4, Nylon, Philips panhead; Manufacturer: B&F Fastener Supply; CompType: Hardware; SymbolCreator: codlsc; U/M: EA; Green_Lifecycle: Not Set; Green_REACh: Incomplete
H5-H8 = 1902C: Standoff, Hex, 0.5"L #4-40 Nylon; Manufacturer: Keystone; Green_Lifecycle: Active; Green_REACh: Passed; SymbolCreator: a0412235
LBL1 = THT-14-423-10: Thermal Transfer Printable Labels, 0.650" W x 0.200" H - 10,000 per roll; Manufacturer: Brady; SymbolCreator: a0412235; CompType: Label; Green_Lifecycle: Not Set; Green_REACh: Incomplete

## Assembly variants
001: not fitted C1 C24 L2 L5 Q1 Q6 R1 R22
